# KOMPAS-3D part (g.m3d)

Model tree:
1. Эскиз:1
2. Операция выдавливания:1
     Расстояние 1 = 20
3. Эскиз:2
4. Вырезать элемент выдавливания:1
     Расстояние 1 = 10
5. Эскиз:3
6. Вырезать элемент выдавливания:2
     Расстояние 1 = 10
7. Эскиз:4
8. Операция выдавливания:2
     Расстояние 1 = 60
9. Эскиз:5
10. Эскиз:6
11. Вырезать элемент выдавливания:3
     Расстояние 1 = 60
12. Эскиз:9
13. Вырезать элемент выдавливания:6
     Расстояние 1 = 80
14. Эскиз:10
15. Вырезать элемент выдавливания:7
     Расстояние 1 = 12
16. Вырезать элемент выдавливания:8
     Расстояние 1 = 60
17. Эскиз:11
18. Вырезать элемент выдавливания:9
     Расстояние 1 = 60
19. Эскиз:12
